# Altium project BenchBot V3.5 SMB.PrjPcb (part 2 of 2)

## Sheet MECHANICAL.SchDoc
size 381 x 241 mm
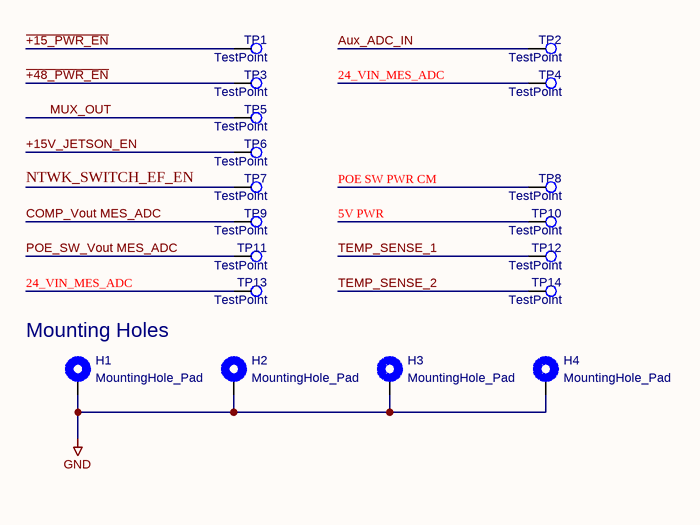
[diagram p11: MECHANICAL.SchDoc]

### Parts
H1  value MountingHole_Pad  [MountingHole_3.2mm_M3_DIN965_Pad]  (hidden comment: Comment)
H2  value MountingHole_Pad  [MountingHole_3.2mm_M3_DIN965_Pad]  (hidden comment: Comment)
H3  value MountingHole_Pad  [MountingHole_3.2mm_M3_DIN965_Pad]  (hidden comment: Comment)
H4  value MountingHole_Pad  [MountingHole_3.2mm_M3_DIN965_Pad]  (hidden comment: Comment)
TP1  value TestPoint  [TestPoint_Pad_D1.0mm]  (hidden comment: Comment)
TP2  value TestPoint  [TestPoint_Pad_D1.0mm]  (hidden comment: Comment)
TP3  value TestPoint  [TestPoint_Pad_D1.0mm]  (hidden comment: Comment)
TP4  value TestPoint  [TestPoint_Pad_D1.0mm]  (hidden comment: Comment)
TP5  value TestPoint  [TestPoint_Pad_D1.0mm]  (hidden comment: Comment)
TP6  value TestPoint  [TestPoint_Pad_D1.0mm]  (hidden comment: Comment)
TP7  value TestPoint  [TestPoint_Pad_D1.0mm]  (hidden comment: Comment)
TP8  value TestPoint  [TestPoint_Pad_D1.0mm]  (hidden comment: Comment)
TP9  value TestPoint  [TestPoint_Pad_D1.0mm]  (hidden comment: Comment)
TP10  value TestPoint  [TestPoint_Pad_D1.0mm]  (hidden comment: Comment)
TP11  value TestPoint  [TestPoint_Pad_D1.0mm]  (hidden comment: Comment)
TP12  value TestPoint  [TestPoint_Pad_D1.0mm]  (hidden comment: Comment)
TP13  value TestPoint  [TestPoint_Pad_D1.0mm]  (hidden comment: Comment)
TP14  value TestPoint  [TestPoint_Pad_D1.0mm]  (hidden comment: Comment)

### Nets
GND: H1.1 H2.1 H3.1 H4.1
5V PWR: TP10.1
24_VIN_MES_ADC: TP4.1 TP13.1
+15V_JETSON_EN: TP6.1
~{+15_PWR_EN}: TP1.1
~{+48_PWR_EN}: TP3.1
Aux_ADC_IN: TP2.1
COMP_Vout MES_ADC: TP9.1
MUX_OUT: TP5.1
NTWK_SWITCH_EF_EN: TP7.1
POE SW PWR CM: TP8.1
POE_SW_Vout MES_ADC: TP11.1
TEMP_SENSE_1: TP12.1
TEMP_SENSE_2: TP14.1

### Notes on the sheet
- (near H1) Mounting Holes

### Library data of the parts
H1-H4 = MountingHole_Pad
TP1-TP14 = TestPoint

## Sheet ADC.SchDoc
size A

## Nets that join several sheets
+3V3: 3V3 PSU (C34.1 C35.1 PS4.3 TP42.1), ADC ARRAY (F7.1), EFUSE0 (D10_EFUSE0.1), I2C EXPANDER (18 pins), TEMPERATURE SENSORS (F6.1), 48V AND 15V PSU (R3.1 R6.1), EFUSE1 (D10_EFUSE1.1), EFUSE2 (D10_EFUSE2.1), EFUSE3 (D10_EFUSE3.1)
+5V: 5V0 PSU (C3.1 C4.1 PS1.3 TP18.1), ADC ARRAY (R26.2), OUTPUT CONNECTORS (F?.2), UART TO RS485 (F5.1)
+15V: ADC ARRAY (R25.2), 48V AND 15V PSU (8 pins), EFUSE3 (U6_EFUSE3.2 U6_EFUSE3.3 U6_EFUSE3.11)
+24V: 3V3 PSU (F10.1), 5V0 PSU (F1.3 F1.4 F2.1 TP17.1), ADC ARRAY (R30.2), 48V AND 15V PSU (D3.1 F3.1 F4.1), EFUSE1 (U6_EFUSE1.10), EFUSE2 (U6_EFUSE2.2 U6_EFUSE2.3 U6_EFUSE2.10 U6_EFUSE2.11), EFUSE3 (U6_EFUSE3.10)
+48V: ADC ARRAY (R29.2), EFUSE0 (U6_EFUSE0.2 U6_EFUSE0.3 U6_EFUSE0.10 U6_EFUSE0.11), 48V AND 15V PSU (8 pins), EFUSE1 (U6_EFUSE1.2 U6_EFUSE1.3 U6_EFUSE1.11)
GND: 3V3 PSU (5 pins), 5V0 PSU (5 pins), ADC ARRAY (8 pins), EFUSE0 (R73_EFUSE0.2 R74_EFUSE0.2 U6_EFUSE0.8 U6_EFUSE0.17), INPUT CONNECTORS (20 pins), OUTPUT CONNECTORS (45 pins), I2C EXPANDER (25 pins), TEMPERATURE SENSORS (C27.2 U2.3 U3.3), UART TO RS485 (C25.2 C26.2 R16.2 U1.5), 48V AND 15V PSU (33 pins), EFUSE1 (R73_EFUSE1.2 R74_EFUSE1.2 U6_EFUSE1.8 U6_EFUSE1.17), EFUSE2 (R73_EFUSE2.2 R74_EFUSE2.2 U6_EFUSE2.8 U6_EFUSE2.17), EFUSE3 (R73_EFUSE3.2 R74_EFUSE3.2 U6_EFUSE3.8 U6_EFUSE3.17), MECHANICAL (H1.1 H2.1 H3.1 H4.1)
JETSON_3V3: INPUT CONNECTORS (J2.1 J3.1), I2C EXPANDER (U?.2)
15V CM: ADC ARRAY (R22.1), 48V AND 15V PSU (C14.1 R2.2 TP21.1)
48V POE EF EN: EFUSE0 (U6_EFUSE0.13 U6_EFUSE0.14 U6_EFUSE0.15 U6_EFUSE0.16), EFUSE1 (U6_EFUSE1.15 U6_EFUSE1.16)
48V_AUX_EF_EN: I2C EXPANDER (R39.1 R40.1 U?.15), EFUSE1 (U6_EFUSE1.14)
+24_VIN: 5V0 PSU (F1.1 F1.2 TP16.1), INPUT CONNECTORS (D11.2 J1.1 J1.3)
~{+15_PWR_EN}: I2C EXPANDER (R?#1.2), 48V AND 15V PSU (PS2.2)
~{+48_PWR_EN}: I2C EXPANDER (IC1.3 TP35.1), 48V AND 15V PSU (PS3.2)
BLUE_EN: OUTPUT CONNECTORS (D29.1 IC8.1), I2C EXPANDER (R69.1 R70.1 U?.11)
EN1: I2C EXPANDER (R33.1 R34.1 R?#2.2), EFUSE3 (U6_EFUSE3.14 U6_EFUSE3.15 U6_EFUSE3.16)
EN4: I2C EXPANDER (IC4.3 R52.1 R53.1 TP39.1), EFUSE1 (U6_EFUSE1.13)
EN4: I2C EXPANDER (R50.1 R51.1), EFUSE3 (U6_EFUSE3.13)
ESTOP_SENSE: OUTPUT CONNECTORS (J10.1), I2C EXPANDER (R55.1 R56.1 R68.1)
ESTOP_TRIG: OUTPUT CONNECTORS (J10.2), I2C EXPANDER (R59.1 R60.1)
GREEN_EN: OUTPUT CONNECTORS (D26.1 IC5.1), I2C EXPANDER (R61.1 R62.1 U?.8)
Jet_UART1_Rx: INPUT CONNECTORS (J2.8 J3.8), UART TO RS485 (R12.2)
Jet_UART1_Rx_IN: INPUT CONNECTORS (J2.10 J3.10), UART TO RS485 (R14.2)
JETSON OUT: OUTPUT CONNECTORS (D13.2 J6.1), EFUSE3 (U6_EFUSE3.1 U6_EFUSE3.4 U6_EFUSE3.12)
OUT3: OUTPUT CONNECTORS (D12.2 J4.1), EFUSE1 (U6_EFUSE1.12)
OUT4: OUTPUT CONNECTORS (D39.2 J12.1), EFUSE1 (U6_EFUSE1.9)
OUT4: OUTPUT CONNECTORS (D16.2 J8.1), EFUSE3 (U6_EFUSE3.9)
POE SW PWR CM: ADC ARRAY (R21.1), 48V AND 15V PSU (C24.1 R5.2 TP25.1)
RED_EN: OUTPUT CONNECTORS (D28.1 IC7.1), I2C EXPANDER (R66.1 R67.1 U?.9)
RS_485_N: OUTPUT CONNECTORS (D15.2 J5.3), UART TO RS485 (R15.2)
RS_485_P: OUTPUT CONNECTORS (D14.2 J5.2), UART TO RS485 (R13.2)
TEMP SENSE 1: ADC ARRAY (R23.1), TEMPERATURE SENSORS (TP27.1 U2.2)
TEMP SENSE 2: ADC ARRAY (R24.1), TEMPERATURE SENSORS (TP28.1 U3.2)
YELLOW_EN: OUTPUT CONNECTORS (D27.1 IC6.1), I2C EXPANDER (R64.1 R65.1 U?.10)

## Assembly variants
Prototype: not fitted R30 R32 R34 R37 R40 R42 R44 R46 R47 R50 R52 R53 R56 R61 R64 R66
